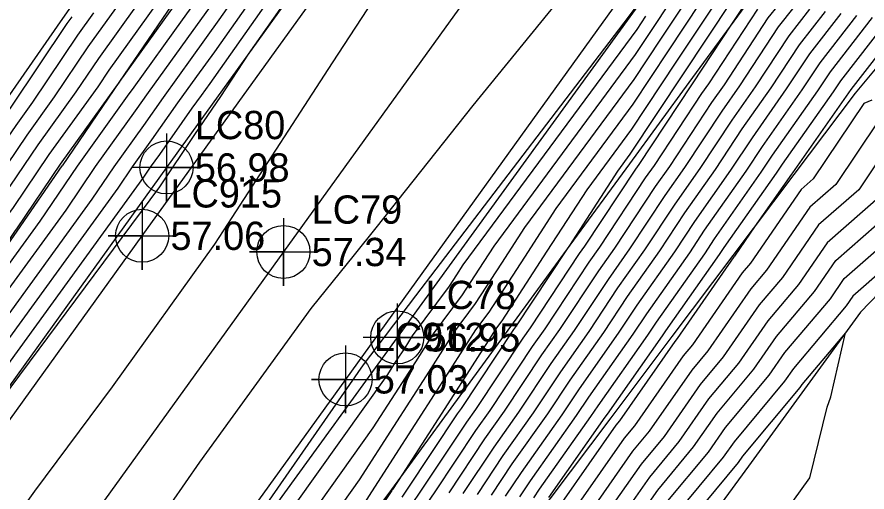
# Model space of a CAD drawing. Extents: x 2188792 to 2191981, y 386090 to 389710.
# Drawn here: x 2189855.4 to 2189930.5, y 387236.6 to 387278.5 of the extents above; entities that cross this region are included whole.
import ezdxf

# ---------------------------------------------------------------- set-up
doc = ezdxf.new("R2010")
doc.units = 0
for name, color, linetype in [('DTM Contours Major', 7, 'Continuous'), ('DTM Contours Minor', 7, 'Continuous'), ('Exist Roads EOP', 7, 'Continuous'), ('Exist Roads EOP Cogo Elevation', 7, 'Continuous'), ('Exist Roads EOP Cogo Number', 7, 'Continuous'), ('Exist Roads EOP Cogo Point CELL', 7, 'Continuous'), ('Exist Roads EOT', 7, 'Continuous'), ('Exist Roads EOT Cogo Elevation', 7, 'Continuous'), ('Exist Roads EOT Cogo Number', 7, 'Continuous'), ('Exist Roads EOT Cogo Point CELL', 7, 'Continuous'), ('PH Exist DTM Breakline', 7, 'Continuous')]:
    doc.layers.add(name, color=color, linetype=linetype)

msp = doc.modelspace()

# ---------------------------------------------------------------- linework, layer by layer
at = {"layer": 'DTM Contours Major'}
for points in [[(2189839.476, 387181.412), (2189856.598, 387205.434), (2189856.62, 387205.466), (2189856.64, 387205.496), (2189856.659, 387205.525), (2189858.223, 387207.732), (2189869.834, 387224.619), (2189877.249, 387235.156), (2189886.017, 387247.794), (2189890.656, 387253.898), (2189892.445, 387256.247), (2189909.424, 387278.537), (2189910.292, 387279.677), (2189910.315, 387279.709), (2189911.35, 387281.066), (2189927.816, 387303.457), (2189927.931, 387303.631), (2189928.041, 387303.798), (2189928.147, 387303.957), (2189928.3, 387304.131), (2189939.5, 387319.43), (2189939.713, 387319.861), (2189939.829, 387320.314), (2189949.954, 387334.279)], [(2189889.131, 387294.16), (2189875.837, 387275.244), (2189873.402, 387271.521), (2189871.117, 387268.163), (2189868.023, 387263.523), (2189851.528, 387241.376), (2189851.153, 387240.864), (2189849.827, 387239.091), (2189836.429, 387220.687), (2189836.321, 387220.571), (2189836.166, 387220.405), (2189836.033, 387220.214), (2189819.116, 387197.803), (2189818.476, 387196.893), (2189817.877, 387196.042), (2189817.316, 387195.246), (2189805.405, 387179.378)], [(2189814.781, 387205.028), (2189819.114, 387210.993), (2189820.392, 387212.776), (2189824.645, 387218.631), (2189825.754, 387220.352), (2189829.968, 387225.621), (2189830.826, 387226.958), (2189835.436, 387232.628), (2189835.992, 387233.498), (2189841.102, 387239.658), (2189841.287, 387239.949), (2189843.591, 387242.658), (2189846.764, 387246.355), (2189851.385, 387251.738), (2189854.777, 387256.754), (2189857.49, 387260.492), (2189860.766, 387265.355), (2189865.205, 387271.534), (2189865.782, 387272.354), (2189870.049, 387278.295), (2189874.071, 387283.895)], [(2189917.132, 387279.855), (2189913.608, 387274.538), (2189909.682, 387268.615), (2189905.738, 387263.266), (2189902.224, 387257.833), (2189898.241, 387251.676), (2189897.783, 387251.057), (2189893.47, 387244.344), (2189889.481, 387238.133), (2189888.58, 387236.778), (2189888.553, 387236.739), (2189888.523, 387236.696), (2189884.166, 387230.195), (2189880.109, 387224.142), (2189879.776, 387223.659), (2189879.425, 387223.149), (2189875.383, 387217.13), (2189874.875, 387216.393), (2189870.987, 387210.609), (2189866.85, 387204.603), (2189865.971, 387203.564), (2189861.814, 387197.539), (2189860.959, 387196.518), (2189856.786, 387190.476)], [(2189924.019, 387279.414), (2189922.658, 387277.662), (2189919.238, 387272.464), (2189917.662, 387270.217), (2189914.386, 387265.249), (2189912.65, 387262.779), (2189909.516, 387258.036), (2189907.625, 387255.348), (2189904.63, 387250.826), (2189902.585, 387247.924), (2189899.728, 387243.618), (2189897.532, 387240.507), (2189894.809, 387236.412)], [(2189814.771, 387211.853), (2189819.239, 387218.082), (2189820.225, 387219.44), (2189823.946, 387225.213), (2189824.855, 387226.349), (2189828.568, 387232.132), (2189829.484, 387233.259), (2189833.187, 387239.053), (2189834.112, 387240.169), (2189837.802, 387245.976), (2189838.739, 387247.078), (2189843.449, 387253.234), (2189844.661, 387254.641), (2189849.066, 387260.374), (2189850.055, 387261.845), (2189854.272, 387267.354), (2189855.357, 387268.963), (2189856.833, 387271.018), (2189860.8, 387276.948), (2189862.222, 387278.923)], [(2189930.94, 387278.483), (2189927.227, 387273.704), (2189926.114, 387272.013), (2189922.116, 387266.315), (2189921.127, 387264.816), (2189916.993, 387258.932), (2189916.126, 387257.621), (2189911.858, 387251.555), (2189911.11, 387250.427), (2189906.711, 387244.184), (2189906.081, 387243.235), (2189901.553, 387236.819), (2189901.039, 387236.046)], [(2189932.804, 387267.819), (2189929.756, 387263.274), (2189926.201, 387260.157), (2189923.014, 387255.523), (2189920.979, 387253.109), (2189917.789, 387248.498), (2189915.758, 387246.064), (2189912.565, 387241.471), (2189910.536, 387239.021), (2189907.341, 387234.445), (2189905.314, 387231.979), (2189902.622, 387227.985), (2189900.541, 387225.436), (2189897.877, 387221.518), (2189895.75, 387218.898), (2189893.094, 387215.036), (2189890.652, 387211.962), (2189888.058, 387208.207), (2189885.5, 387204.992), (2189882.969, 387201.342), (2189879.583, 387197.342), (2189877.107, 387194.231), (2189873.571, 387190.068)], [(2189923.929, 387235.705), (2189925.452, 387237.807), (2189926.977, 387244.043), (2189927.282, 387244.973), (2189928.583, 387250.616), (2189924.745, 387246.063), (2189924.568, 387245.806), (2189919.492, 387239.726), (2189919.1, 387239.163), (2189914.242, 387233.296)]]:
    msp.add_lwpolyline(points, dxfattribs=at)
at = {"layer": 'DTM Contours Minor'}
for points in [[(2189806.103, 387171.079), (2189818.83, 387185.769), (2189823.977, 387192.841), (2189832.146, 387202.524), (2189840.636, 387214.199), (2189849.542, 387226.21), (2189857.019, 387236.627), (2189863.862, 387245.866), (2189872.906, 387258.466), (2189874.441, 387260.833), (2189883.298, 387274.48), (2189889.961, 387284.755), (2189894.836, 387292.266), (2189899.699, 387299.764), (2189911.601, 387317.434), (2189912.049, 387318.099), (2189914.929, 387322.013), (2189928.336, 387339.246)], [(2189937.835, 387325.802), (2189928.451, 387313.821), (2189924.705, 387308.455), (2189912.794, 387292.052), (2189906.641, 387284.303), (2189906.065, 387283.51), (2189895.672, 387270.72), (2189887.112, 387259.916), (2189885.216, 387257.522), (2189881.384, 387252.787), (2189871.553, 387239.191), (2189863.95, 387228.232), (2189855.914, 387217.121), (2189849.603, 387208.007), (2189840.533, 387195.387), (2189832.223, 387183.387), (2189825.819, 387174.474), (2189818.869, 387164.423), (2189809.4, 387152.406)], [(2189849.089, 387187.083), (2189855.514, 387196.097), (2189858.561, 387200.607), (2189861.481, 387204.929), (2189864.282, 387209.076), (2189870.405, 387217.719), (2189872.925, 387221.801), (2189874.972, 387225.117), (2189876.668, 387227.865), (2189886.895, 387242.237), (2189888.817, 387245.23), (2189890.642, 387248.071), (2189892.222, 387250.529), (2189894.767, 387253.972), (2189896.249, 387256.263), (2189897.556, 387258.284), (2189910.059, 387275.238), (2189911.623, 387277.599), (2189913.027, 387279.718), (2189914.163, 387281.453), (2189926.879, 387298.745), (2189928.163, 387300.687), (2189929.39, 387302.543), (2189930.564, 387304.318)], [(2189854.972, 387191.429), (2189859.531, 387198.177), (2189863.901, 387204.646), (2189868.093, 387210.851), (2189869.874, 387213.364), (2189873.73, 387219.611), (2189876.862, 387224.686), (2189879.457, 387228.89), (2189885.676, 387237.63), (2189888.707, 387242.349), (2189891.585, 387246.828), (2189894.076, 387250.705), (2189895.925, 387253.206), (2189898.24, 387256.786), (2189900.284, 387259.945), (2189909.933, 387273.03), (2189912.284, 387276.578), (2189914.395, 387279.764), (2189916.102, 387282.372), (2189926.411, 387296.39), (2189928.279, 387299.215), (2189930.064, 387301.916), (2189931.772, 387304.499)], [(2189886.854, 387293.151), (2189872.459, 387272.671), (2189871.692, 387271.603), (2189870.878, 387270.469), (2189868.011, 387266.389), (2189867.203, 387265.264), (2189866.606, 387264.378), (2189851.846, 387244.042), (2189851.172, 387243.045), (2189850.253, 387241.975), (2189849.094, 387240.624), (2189847.585, 387238.866), (2189836.443, 387223.561), (2189834.943, 387221.952), (2189832.814, 387219.669), (2189830.965, 387217.02), (2189819.697, 387202.092), (2189817.42, 387198.857), (2189815.292, 387195.834)], [(2189884.576, 387292.143), (2189872.862, 387275.477), (2189871.281, 387273.276), (2189869.604, 387270.941), (2189867.31, 387267.675), (2189865.594, 387265.286), (2189864.327, 387263.407), (2189852.579, 387247.22), (2189851.225, 387245.219), (2189849.381, 387243.07), (2189847.054, 387240.358), (2189844.024, 387236.829), (2189836.458, 387226.435), (2189833.566, 387223.334), (2189829.461, 387218.933), (2189825.898, 387213.827), (2189820.277, 387206.38), (2189816.364, 387200.821), (2189812.707, 387195.626)], [(2189882.298, 387291.135), (2189873.265, 387278.283), (2189870.87, 387274.949), (2189868.33, 387271.412), (2189866.608, 387268.961), (2189863.984, 387265.309), (2189862.048, 387262.435), (2189853.312, 387250.398), (2189851.278, 387247.392), (2189848.509, 387244.165), (2189845.013, 387240.093), (2189840.463, 387234.791), (2189836.472, 387229.308), (2189832.189, 387224.716), (2189827.515, 387219.705), (2189826.478, 387218.408), (2189826.413, 387218.308), (2189820.854, 387210.653), (2189820.851, 387210.649), (2189820.628, 387210.343), (2189815.308, 387202.785)], [(2189814.996, 387203.957), (2189819.982, 387210.821), (2189820.623, 387211.715), (2189825.529, 387218.469), (2189826.116, 387219.38), (2189830.99, 387225.475), (2189831.278, 387225.923), (2189835.553, 387231.182), (2189836.486, 387232.182), (2189836.902, 387232.753), (2189842.973, 387239.827), (2189847.637, 387245.26), (2189851.331, 387249.565), (2189854.044, 387253.576), (2189859.769, 387261.463), (2189862.375, 387265.332), (2189865.907, 387270.247), (2189867.056, 387271.883), (2189870.46, 387276.622), (2189873.668, 387281.089)], [(2189814.349, 387207.169), (2189817.377, 387211.337), (2189819.931, 387214.898), (2189822.877, 387218.955), (2189825.031, 387222.296), (2189827.923, 387225.912), (2189829.923, 387229.028), (2189833.055, 387232.88), (2189834.87, 387235.72), (2189838.306, 387239.862), (2189839.893, 387242.36), (2189843.723, 387246.863), (2189845.39, 387249.042), (2189849.713, 387254.058), (2189850.833, 387255.517), (2189853.994, 387260.214), (2189855.125, 387261.692), (2189858.289, 387266.384), (2189862.592, 387272.379), (2189863.579, 387273.853), (2189867.998, 387279.994)], [(2189814.565, 387206.098), (2189818.245, 387211.165), (2189820.162, 387213.837), (2189823.761, 387218.793), (2189825.393, 387221.324), (2189828.945, 387225.767), (2189830.374, 387227.993), (2189834.246, 387232.754), (2189835.431, 387234.609), (2189839.704, 387239.76), (2189840.59, 387241.154), (2189845.384, 387246.791), (2189846.037, 387247.645), (2189851.396, 387253.864), (2189851.422, 387253.898), (2189855.307, 387259.671), (2189855.409, 387259.804), (2189859.267, 387265.524), (2189864.306, 387272.545), (2189864.504, 387272.82), (2189864.508, 387272.826), (2189869.638, 387279.969)], [(2189915.764, 387279.809), (2189912.946, 387275.558), (2189909.808, 387270.823), (2189903.011, 387261.605), (2189900.232, 387257.31), (2189897.083, 387252.441), (2189895.929, 387250.881), (2189892.528, 387245.586), (2189888.597, 387239.468), (2189884.457, 387233.023), (2189882.247, 387229.916), (2189878.752, 387224.255), (2189876.959, 387221.35), (2189874.542, 387217.75), (2189874.454, 387217.622), (2189870.15, 387211.219), (2189865.569, 387204.571), (2189865.22, 387204.158), (2189860.646, 387197.528), (2189860.285, 387197.097), (2189855.717, 387190.484)], [(2189918.5, 387279.901), (2189914.269, 387273.517), (2189909.557, 387266.407), (2189908.465, 387264.927), (2189904.216, 387258.357), (2189903.967, 387257.973), (2189899.446, 387251.145), (2189899.284, 387250.916), (2189894.645, 387243.924), (2189894.315, 387243.457), (2189889.825, 387236.705), (2189889.405, 387236.091)], [(2189919.868, 387279.947), (2189918.454, 387277.813), (2189915.112, 387272.734), (2189914.989, 387272.558), (2189910.341, 387265.509), (2189910.045, 387265.087), (2189905.551, 387258.286), (2189905.085, 387257.624), (2189900.742, 387251.065), (2189900.11, 387250.168), (2189895.915, 387243.847), (2189895.12, 387242.72), (2189891.071, 387236.631), (2189890.258, 387235.443)], [(2189813.917, 387209.31), (2189815.639, 387211.681), (2189819.469, 387217.021), (2189821.109, 387219.278), (2189824.308, 387224.241), (2189825.878, 387226.204), (2189829.02, 387231.097), (2189830.675, 387233.133), (2189833.748, 387237.942), (2189835.51, 387240.066), (2189838.499, 387244.771), (2189840.4, 387247.006), (2189844.096, 387251.837), (2189846.345, 387254.447), (2189849.655, 387258.755), (2189851.368, 387261.301), (2189854.556, 387265.467), (2189856.335, 387268.103), (2189858.752, 387271.472), (2189861.727, 387275.916), (2189864.147, 387279.28)], [(2189814.133, 387208.239), (2189816.508, 387211.509), (2189819.7, 387215.959), (2189821.993, 387219.116), (2189824.669, 387223.269), (2189826.9, 387226.058), (2189829.471, 387230.062), (2189831.865, 387233.007), (2189834.309, 387236.831), (2189836.908, 387239.964), (2189839.196, 387243.565), (2189842.061, 387246.935), (2189844.743, 387250.439), (2189848.029, 387254.252), (2189850.244, 387257.136), (2189852.681, 387260.758), (2189854.84, 387263.579), (2189857.312, 387267.243), (2189860.672, 387271.925), (2189862.653, 387274.885), (2189866.072, 387279.637)], [(2189920.831, 387279.245), (2189916.488, 387272.644), (2189915.88, 387271.778), (2189911.689, 387265.422), (2189910.913, 387264.318), (2189906.873, 387258.203), (2189905.931, 387256.865), (2189902.038, 387250.986), (2189900.935, 387249.42), (2189897.186, 387243.771), (2189895.924, 387241.982), (2189892.317, 387236.558), (2189891.11, 387234.795)], [(2189922.635, 387279.6), (2189921.744, 387278.454), (2189917.863, 387272.554), (2189916.771, 387270.997), (2189913.038, 387265.335), (2189911.782, 387263.548), (2189908.195, 387258.119), (2189906.778, 387256.107), (2189903.334, 387250.906), (2189901.76, 387248.672), (2189898.457, 387243.694), (2189896.728, 387241.245), (2189893.563, 387236.485)], [(2189925.403, 387279.228), (2189923.572, 387276.87), (2189920.613, 387272.373), (2189918.552, 387269.437), (2189915.734, 387265.162), (2189913.519, 387262.01), (2189910.838, 387257.953), (2189908.471, 387254.59), (2189905.926, 387250.746), (2189903.41, 387247.176), (2189900.998, 387243.541), (2189898.336, 387239.769), (2189896.055, 387236.339)], [(2189926.788, 387279.041), (2189924.486, 387276.079), (2189921.989, 387272.283), (2189919.443, 387268.656), (2189917.083, 387265.076), (2189914.387, 387261.24), (2189912.16, 387257.87), (2189909.318, 387253.831), (2189907.222, 387250.666), (2189904.235, 387246.428), (2189902.269, 387243.465), (2189899.141, 387239.032), (2189897.301, 387236.265)], [(2189813.902, 387212.025), (2189819.008, 387219.143), (2189819.341, 387219.602), (2189823.585, 387226.185), (2189823.832, 387226.495), (2189828.116, 387233.167), (2189828.294, 387233.385), (2189832.626, 387240.164), (2189832.714, 387240.271), (2189836.156, 387245.688), (2189836.965, 387247.175), (2189837.038, 387247.308), (2189837.929, 387248.262), (2189842.802, 387254.631), (2189842.978, 387254.835), (2189848.476, 387261.993), (2189848.742, 387262.388), (2189853.988, 387269.242), (2189854.38, 387269.823), (2189854.913, 387270.565), (2189859.874, 387277.98), (2189860.296, 387278.567)], [(2189844.282, 387184.248), (2189856.056, 387200.766), (2189857.59, 387203.036), (2189859.06, 387205.212), (2189860.471, 387207.3), (2189870.937, 387222.073), (2189872.12, 387223.99), (2189873.082, 387225.548), (2189873.878, 387226.839), (2189888.114, 387246.845), (2189888.927, 387248.111), (2189889.699, 387249.313), (2189890.368, 387250.353), (2189893.609, 387254.737), (2189894.257, 387255.739), (2189894.829, 387256.623), (2189910.184, 387277.446), (2189910.961, 387278.619)], [(2189928.172, 387278.855), (2189925.399, 387275.287), (2189923.364, 387272.193), (2189920.334, 387267.876), (2189918.431, 387264.989), (2189915.256, 387260.471), (2189913.482, 387257.787), (2189910.164, 387253.073), (2189908.518, 387250.587), (2189905.061, 387245.68), (2189903.54, 387243.388), (2189899.945, 387238.294), (2189898.547, 387236.192)], [(2189929.556, 387278.669), (2189926.313, 387274.495), (2189924.739, 387272.103), (2189921.225, 387267.095), (2189919.779, 387264.902), (2189916.124, 387259.702), (2189914.804, 387257.704), (2189911.011, 387252.314), (2189909.814, 387250.507), (2189905.886, 387244.932), (2189904.811, 387243.312), (2189900.749, 387237.556), (2189899.793, 387236.119)], [(2189932.325, 387278.297), (2189928.14, 387272.912), (2189927.49, 387271.923), (2189923.007, 387265.535), (2189922.476, 387264.729), (2189917.861, 387258.163), (2189917.448, 387257.537), (2189912.704, 387250.797), (2189912.406, 387250.347), (2189907.536, 387243.436), (2189907.352, 387243.159), (2189902.357, 387236.081)], [(2189933.709, 387278.111), (2189929.054, 387272.121), (2189928.865, 387271.833), (2189923.898, 387264.754), (2189923.824, 387264.643), (2189920.562, 387260.001), (2189918.778, 387257.406), (2189918.72, 387257.337), (2189913.723, 387250.113), (2189913.517, 387249.867), (2189908.644, 387242.856), (2189908.312, 387242.455), (2189903.547, 387235.63)], [(2189930.927, 387271.181), (2189930.198, 387270.89), (2189925.73, 387264.228), (2189924.679, 387263.307), (2189920.19, 387256.779), (2189919.473, 387255.928), (2189915.078, 387249.574), (2189914.264, 387248.599), (2189909.951, 387242.395), (2189909.053, 387241.31), (2189904.811, 387235.235), (2189903.841, 387234.055), (2189900.322, 387228.832), (2189899.206, 387227.466), (2189895.772, 387222.415), (2189894.534, 387220.89), (2189891.151, 387215.972), (2189889.671, 387214.109), (2189886.355, 387209.307), (2189884.75, 387207.29), (2189881.499, 387202.602), (2189877.15, 387197.465), (2189875.655, 387195.587), (2189871.093, 387190.216)], [(2189931.501, 387269.354), (2189927.743, 387263.751), (2189925.44, 387261.732), (2189921.602, 387256.151), (2189920.226, 387254.518), (2189916.434, 387249.036), (2189915.011, 387247.331), (2189911.258, 387241.933), (2189909.795, 387240.166), (2189906.076, 387234.84), (2189904.578, 387233.017), (2189901.472, 387228.409), (2189899.874, 387226.451), (2189896.825, 387221.967), (2189895.142, 387219.894), (2189892.123, 387215.504), (2189890.162, 387213.036), (2189887.207, 387208.757), (2189885.125, 387206.141), (2189882.234, 387201.972), (2189878.366, 387197.403), (2189876.381, 387194.909), (2189872.332, 387190.142)], [(2189931.769, 387262.797), (2189926.961, 387258.582), (2189924.426, 387254.896), (2189921.732, 387251.7), (2189919.145, 387247.959), (2189916.504, 387244.796), (2189913.872, 387241.01), (2189911.277, 387237.876), (2189908.606, 387234.05), (2189906.051, 387230.941), (2189903.772, 387227.561), (2189901.208, 387224.42), (2189898.93, 387221.07), (2189896.358, 387217.902), (2189894.065, 387214.568), (2189891.142, 387210.889), (2189888.91, 387207.657), (2189885.876, 387203.843), (2189883.704, 387200.712), (2189880.8, 387197.28), (2189877.833, 387193.554)], [(2189896.966, 387216.906), (2189899.983, 387220.621), (2189901.875, 387223.405), (2189904.923, 387227.137), (2189906.787, 387229.904), (2189909.871, 387233.654), (2189912.018, 387236.731), (2189915.179, 387240.548), (2189917.251, 387243.529), (2189920.501, 387247.421), (2189922.486, 387250.291), (2189925.839, 387254.268), (2189927.722, 387257.007), (2189933.782, 387262.319)], [(2189897.574, 387215.91), (2189901.035, 387220.173), (2189902.543, 387222.39), (2189906.073, 387226.713), (2189907.523, 387228.866), (2189911.135, 387233.259), (2189912.76, 387235.586), (2189916.486, 387240.086), (2189917.998, 387242.261), (2189921.856, 387246.883), (2189923.239, 387248.881), (2189927.251, 387253.641), (2189928.483, 387255.432), (2189935.796, 387261.842)], [(2189937.809, 387261.365), (2189929.243, 387253.857), (2189928.663, 387253.013), (2189923.992, 387247.472), (2189923.212, 387246.344), (2189918.745, 387240.994), (2189917.793, 387239.625), (2189913.501, 387234.441), (2189912.4, 387232.864), (2189908.26, 387227.828), (2189907.223, 387226.289), (2189903.21, 387221.375), (2189902.088, 387219.725), (2189898.183, 387214.914), (2189896.979, 387213.164), (2189892.613, 387207.669), (2189891.465, 387206.007), (2189887.001, 387200.396), (2189885.91, 387198.822), (2189884.449, 387197.096), (2189880.01, 387191.52)]]:
    msp.add_lwpolyline(points, dxfattribs=at)
at = {"layer": 'Exist Roads EOP'}
for points in [[(2190313.986, 387884.141), (2190285.547, 387843.636), (2190254.588, 387800.045), (2190225.155, 387759.32), (2190194.829, 387717.425), (2190164.291, 387675.101), (2190137.229, 387637.301), (2190105.098, 387592.774), (2190071.411, 387546.221), (2190039.296, 387501.568), (2190007.542, 387457.958), (2189976.844, 387415.407), (2189936.359, 387359.145), (2189907.138, 387318.716), (2189868.636, 387265.243), (2189836.428, 387220.463), (2189805.695, 387177.815), (2189775.592, 387135.957), (2189745.498, 387094.055), (2189715.496, 387052.249), (2189683.869, 387008.07), (2189653.218, 386965.867), (2189623.729, 386924.667)], [(2190335.128, 387868.989), (2190306.373, 387829.271), (2190274.581, 387784.921), (2190245.133, 387744.071), (2190214.553, 387701.741), (2190184.89, 387660.475), (2190157.493, 387622.204), (2190126.048, 387578.501), (2190091.216, 387530.568), (2190059.634, 387486.726), (2190026.932, 387441.783), (2189997.689, 387401.032), (2189957.023, 387344.154), (2189927.908, 387303.922), (2189889.008, 387250.224), (2189856.606, 387205.5), (2189825.68, 387162.612), (2189795.668, 387120.822), (2189765.955, 387079.619), (2189734.998, 387036.704), (2189703.849, 386993.356), (2189673.984, 386951.979), (2189643.253, 386909.427)]]:
    msp.add_lwpolyline(points, dxfattribs=at)
at = {"layer": 'Exist Roads EOP Cogo Point CELL'}
for points in [[(2189868.636, 387268.243), (2189868.636, 387262.243), (2189868.636, 387265.243), (2189871.636, 387265.243), (2189865.636, 387265.243)], [(2189889.008, 387253.224), (2189889.008, 387247.224), (2189889.008, 387250.224), (2189892.008, 387250.224), (2189886.008, 387250.224)]]:
    msp.add_lwpolyline(points, dxfattribs=at)
for centre in [(2189868.636, 387265.243), (2189889.008, 387250.224)]:
    msp.add_circle(centre, 2.344, dxfattribs=at)
at = {"layer": 'Exist Roads EOT'}
for points in [[(2190174.375, 387667.889), (2190147.471, 387630.495), (2190115.247, 387585.778), (2190081.202, 387538.232), (2190049.502, 387494.256), (2190017.538, 387450.182), (2189987.334, 387408.357), (2189946.666, 387352.019), (2189917.402, 387311.129), (2189878.955, 387257.772), (2189846.565, 387212.819), (2189815.837, 387170.306), (2189785.374, 387128.351), (2189755.717, 387086.921), (2189724.953, 387044.041), (2189693.727, 387000.805), (2189663.933, 386959.217), (2189633.425, 386917.196)], [(2189989.253, 387391.986), (2189958.581, 387349.453), (2189928.09, 387307.216), (2189909.67, 387281.603), (2189884.44, 387246.513), (2189852.91, 387202.766), (2189821.507, 387159.305), (2189790.01, 387115.85), (2189759.16, 387072.957), (2189728.247, 387029.91), (2189696.407, 386985.689), (2189665.45, 386942.736), (2189635.049, 386900.502)], [(2189619.904, 386917.168), (2189650.19, 386959.038), (2189680.959, 387001.734), (2189713.171, 387046.57), (2189739.87, 387083.883), (2189771.556, 387127.847), (2189803.188, 387171.311), (2189835.065, 387215.496), (2189866.485, 387259.202), (2189892.308, 387295.019), (2189910.407, 387320.236), (2189942.075, 387364.22)]]:
    msp.add_lwpolyline(points, dxfattribs=at)
at = {"layer": 'Exist Roads EOT Cogo Point CELL'}
for points in [[(2189866.485, 387262.202), (2189866.485, 387256.202), (2189866.485, 387259.202), (2189863.485, 387259.202), (2189869.485, 387259.202)], [(2189878.955, 387260.772), (2189878.955, 387254.772), (2189878.955, 387257.772), (2189875.955, 387257.772), (2189881.955, 387257.772)], [(2189884.44, 387249.513), (2189884.44, 387243.513), (2189884.44, 387246.513), (2189881.44, 387246.513), (2189887.44, 387246.513)]]:
    msp.add_lwpolyline(points, dxfattribs=at)
for centre in [(2189866.485, 387259.202), (2189878.955, 387257.772), (2189884.44, 387246.513)]:
    msp.add_circle(centre, 2.344, dxfattribs=at)
at = {"layer": 'PH Exist DTM Breakline'}
for points in [[(2189853.827, 387270.309), (2189859.482, 387278.416), (2189865.137, 387286.523), (2189870.792, 387294.63), (2189876.447, 387302.737), (2189882.103, 387310.844), (2189887.345, 387318.68), (2189892.587, 387326.516)], [(2189900.038, 387325.521), (2189894.923, 387317.812), (2189889.808, 387310.103), (2189884.746, 387302.648), (2189879.684, 387295.193), (2189874.623, 387287.738), (2189869.561, 387280.284), (2189864.499, 387272.829), (2189859.437, 387265.374)], [(2189944.497, 387320.037), (2189940.822, 387310.798), (2189937.576, 387305.365), (2189933.186, 387299.012), (2189928.796, 387292.658), (2189924.406, 387286.305), (2189920.015, 387279.952), (2189914.762, 387272.757), (2189909.509, 387265.562), (2189904.255, 387258.367), (2189899.002, 387251.173), (2189893.748, 387243.978), (2189888.495, 387236.783)], [(2189963.399, 387314.577), (2189958.981, 387307.188), (2189954.532, 387301.885), (2189950.082, 387296.583), (2189944.919, 387290.386), (2189939.756, 387284.189), (2189934.592, 387277.992), (2189929.429, 387271.796), (2189924.041, 387264.629), (2189918.653, 387257.462), (2189913.265, 387250.294), (2189907.877, 387243.127), (2189902.489, 387235.96), (2189897.664, 387229.812), (2189892.84, 387223.664), (2189888.163, 387217.412), (2189883.486, 387211.159), (2189878.809, 387204.907), (2189873.445, 387197.651), (2189868.08, 387190.396)], [(2189950.259, 387270.147), (2189944.33, 387265.686), (2189938.4, 387261.225), (2189929.921, 387252.454), (2189924.967, 387245.647), (2189920.013, 387238.84), (2189915.06, 387232.033), (2189910.106, 387225.227), (2189905.152, 387218.42), (2189900.198, 387211.613), (2189894.169, 387204.262), (2189888.14, 387196.91), (2189882.11, 387189.559), (2189876.646, 387182.203), (2189871.181, 387174.848), (2189865.716, 387167.492), (2189860.251, 387160.136), (2189855.22, 387153.995), (2189850.188, 387147.855), (2189846.875, 387141.948), (2189843.562, 387136.041), (2189840.249, 387130.133), (2189836.712, 387120.427)], [(2189755.77, 387138.982), (2189763.02, 387141.08), (2189767.474, 387144.445), (2189776.546, 387153.145), (2189781.956, 387159.882), (2189787.366, 387166.618), (2189792.776, 387173.355), (2189798.186, 387180.091), (2189803.853, 387187.73), (2189809.52, 387195.37), (2189815.188, 387203.009), (2189820.855, 387210.648), (2189826.522, 387218.288), (2189831.505, 387225.402), (2189836.488, 387232.516), (2189841.471, 387239.631), (2189846.454, 387246.745), (2189851.437, 387253.86), (2189855.437, 387259.617), (2189859.437, 387265.374)], [(2189888.495, 387236.783), (2189883.785, 387230.482), (2189879.075, 387224.181), (2189874.366, 387217.88), (2189869.656, 387211.579), (2189864.725, 387204.549), (2189859.794, 387197.519), (2189854.863, 387190.49), (2189849.932, 387183.46), (2189844.544, 387175.116), (2189839.156, 387166.772), (2189833.698, 387158.46), (2189828.24, 387150.149), (2189823.03, 387143.525), (2189817.819, 387136.902), (2189809.372, 387127.264), (2189805.132, 387120.57), (2189803.345, 387115.661), (2189803.11, 387109.54), (2189802.322, 387100.55)]]:
    msp.add_lwpolyline(points, dxfattribs=at)

# ---------------------------------------------------------------- texts
at = {"layer": 'Exist Roads EOP Cogo Elevation'}
for s, p in [('56.98', (2189871.136, 387263.993)), ('56.95', (2189891.508, 387248.974))]:
    msp.add_text(s, height=2.5, dxfattribs=at).set_placement(p)
at = {"layer": 'Exist Roads EOP Cogo Number'}
for s, p in [('LC80', (2189871.136, 387267.743)), ('LC78', (2189891.508, 387252.724))]:
    msp.add_text(s, height=2.5, dxfattribs=at).set_placement(p)
at = {"layer": 'Exist Roads EOT Cogo Elevation'}
for s, p in [('57.06', (2189868.985, 387257.952)), ('57.34', (2189881.455, 387256.522)), ('57.03', (2189886.94, 387245.263))]:
    msp.add_text(s, height=2.5, dxfattribs=at).set_placement(p)
at = {"layer": 'Exist Roads EOT Cogo Number'}
for s, p in [('LC915', (2189868.985, 387261.702)), ('LC79', (2189881.455, 387260.272)), ('LC912', (2189886.94, 387249.013))]:
    msp.add_text(s, height=2.5, dxfattribs=at).set_placement(p)

doc.saveas('drawing.dxf')
